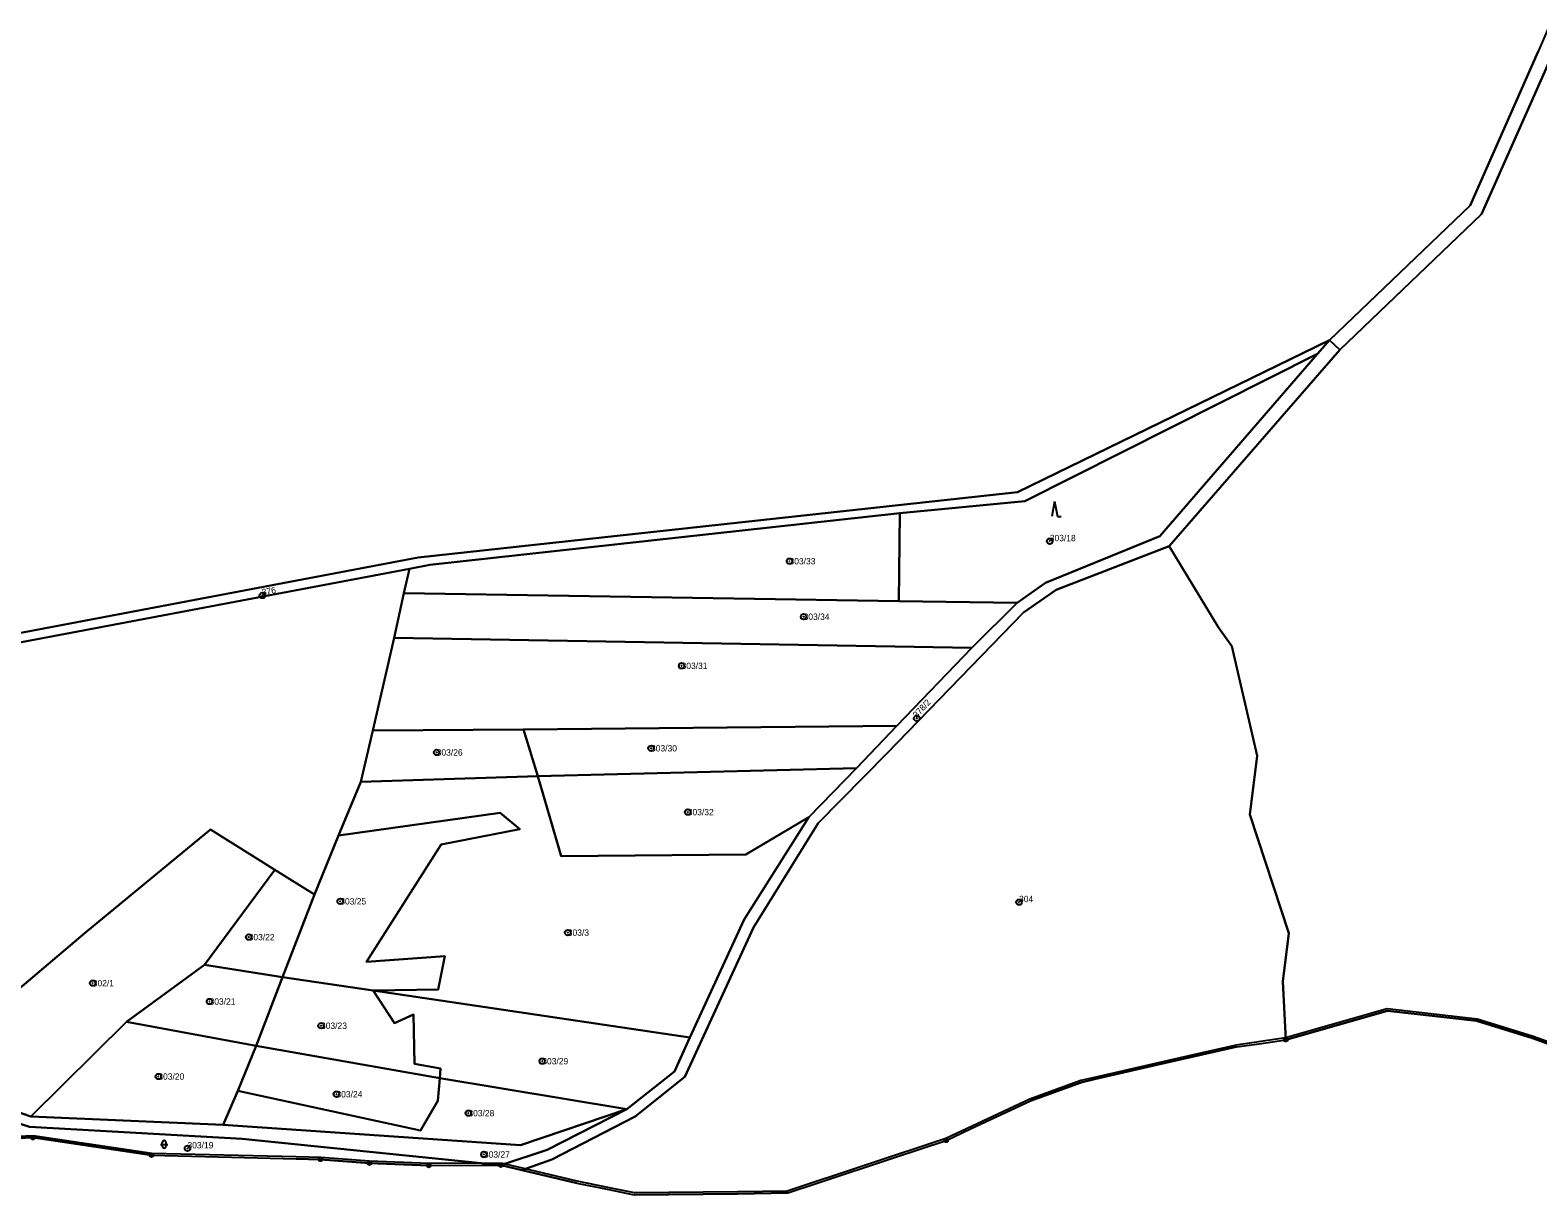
# Model space of a CAD drawing. Extents: x -652854 to -650068, y -1097661 to -1095417.
# Drawn here: x -651701 to -651296.9, y -1097620.5 to -1097308.5 of the extents above; entities that cross this region are included whole.
import ezdxf

# ---------------------------------------------------------------- set-up
doc = ezdxf.new("R2010")
doc.units = 0
for name, color, linetype in [('Definiční body parcel', 7, 'Continuous'), ('Geodetické body', 7, 'Continuous'), ('Hranice obcí', 7, 'Continuous'), ('Hranice parcel', 7, 'Continuous'), ('Obvody jako plochy', 7, 'Continuous'), ('Ostatní hranice', 7, 'Continuous'), ('Parcelní čísla', 7, 'Continuous'), ('Značky kultur', 7, 'Continuous')]:
    doc.layers.add(name, color=color, linetype=linetype)

msp = doc.modelspace()

# ---------------------------------------------------------------- linework, layer by layer
at = {"layer": 'Definiční body parcel'}
for centre, radius in [((-651427.69, -1097445.42), 0.75), ((-651427.69, -1097445.42), 0.0327), ((-651497.45, -1097450.77), 0.75), ((-651497.45, -1097450.77), 0.0327), ((-651638.74, -1097459.95), 0.75), ((-651638.74, -1097459.95), 0.0327), ((-651493.67, -1097465.65), 0.75), ((-651493.67, -1097465.65), 0.0327), ((-651526.38, -1097478.79), 0.75), ((-651526.38, -1097478.79), 0.0327), ((-651463.34, -1097492.88), 0.75), ((-651463.34, -1097492.88), 0.0327), ((-651592.02, -1097502.01), 0.75), ((-651592.02, -1097502.01), 0.0327), ((-651534.57, -1097500.9), 0.75), ((-651534.57, -1097500.9), 0.0327), ((-651524.72, -1097518), 0.75), ((-651524.72, -1097518), 0.0327), ((-651617.87, -1097541.9), 0.75), ((-651617.87, -1097541.9), 0.0327), ((-651435.92, -1097542.13), 0.75), ((-651435.92, -1097542.13), 0.0327), ((-651642.41, -1097551.49), 0.75), ((-651642.41, -1097551.49), 0.0327), ((-651556.88, -1097550.29), 0.75), ((-651556.88, -1097550.29), 0.0327), ((-651684.2, -1097563.83), 0.75), ((-651684.2, -1097563.83), 0.0327), ((-651652.9, -1097568.74), 0.75), ((-651652.9, -1097568.74), 0.0327), ((-651623.02, -1097575.23), 0.75), ((-651623.02, -1097575.23), 0.0327), ((-651563.72, -1097584.73), 0.75), ((-651666.62, -1097588.84), 0.75), ((-651563.72, -1097584.73), 0.0327), ((-651666.62, -1097588.84), 0.0327), ((-651618.89, -1097593.59), 0.75), ((-651618.89, -1097593.59), 0.0327), ((-651583.52, -1097598.66), 0.75), ((-651583.52, -1097598.66), 0.0327), ((-651658.82, -1097608.1), 0.75), ((-651658.82, -1097608.1), 0.0327), ((-651579.35, -1097609.72), 0.75), ((-651579.35, -1097609.72), 0.0327)]:
    msp.add_circle(centre, radius, dxfattribs=at)
at = {"layer": 'Geodetické body'}
for centre, radius in [((-651364.42, -1097579), 0.5), ((-651364.42, -1097579), 0.5), ((-651364.42, -1097579), 0.001), ((-651364.42, -1097579), 0.001), ((-651700.22, -1097605.21), 0.5), ((-651700.22, -1097605.21), 0.001), ((-651455.46, -1097605.96), 0.5), ((-651455.46, -1097605.96), 0.5), ((-651455.46, -1097605.96), 0.001), ((-651455.46, -1097605.96), 0.001), ((-651668.43, -1097609.93), 0.5), ((-651668.43, -1097609.93), 0.001), ((-651623.13, -1097611.06), 0.5), ((-651623.13, -1097611.06), 0.5), ((-651623.13, -1097611.06), 0.001), ((-651623.13, -1097611.06), 0.001), ((-651610.03, -1097612.05), 0.5), ((-651610.03, -1097612.05), 0.5), ((-651610.03, -1097612.05), 0.001), ((-651610.03, -1097612.05), 0.001), ((-651594.11, -1097612.69), 0.5), ((-651594.11, -1097612.69), 0.001), ((-651574.8, -1097612.59), 0.5), ((-651574.8, -1097612.59), 0.5), ((-651574.8, -1097612.59), 0.001), ((-651574.8, -1097612.59), 0.001)]:
    msp.add_circle(centre, radius, dxfattribs=at)
at = {"layer": 'Hranice obcí'}
for p, q in [((-651337.13, -1097571.24), (-651364.42, -1097579)), ((-651313.28, -1097573.95), (-651337.13, -1097571.24)), ((-651298.31, -1097578.57), (-651313.28, -1097573.95)), ((-651377.63, -1097580.93), (-651371.6, -1097580.05)), ((-651371.6, -1097580.05), (-651364.42, -1097579)), ((-651277, -1097586.21), (-651298.31, -1097578.57)), ((-651389.47, -1097583.6), (-651398.89, -1097585.75)), ((-651377.63, -1097580.93), (-651389.47, -1097583.6)), ((-651398.89, -1097585.75), (-651415.59, -1097589.57)), ((-651419.25, -1097590.4), (-651432.82, -1097595.37)), ((-651415.59, -1097589.57), (-651419.25, -1097590.4)), ((-651448.91, -1097602.9), (-651432.82, -1097595.37)), ((-651455.46, -1097605.96), (-651448.91, -1097602.9)), ((-651700.22, -1097605.21), (-651729.58, -1097606.47)), ((-651668.43, -1097609.93), (-651700.22, -1097605.21)), ((-651469.31, -1097610.54), (-651455.46, -1097605.96)), ((-651668.43, -1097609.93), (-651647.03, -1097610.47)), ((-651647.03, -1097610.47), (-651629.7, -1097610.9)), ((-651623.13, -1097611.06), (-651629.7, -1097610.9)), ((-651610.03, -1097612.05), (-651623.13, -1097611.06)), ((-651594.11, -1097612.69), (-651610.03, -1097612.05)), ((-651594.11, -1097612.69), (-651579.78, -1097612.61)), ((-651579.78, -1097612.61), (-651574.8, -1097612.59)), ((-651569.22, -1097613.9), (-651574.8, -1097612.59)), ((-651490.01, -1097617.39), (-651469.31, -1097610.54)), ((-651554.46, -1097617.39), (-651569.22, -1097613.9)), ((-651554.46, -1097617.39), (-651546.31, -1097619.06)), ((-651546.31, -1097619.06), (-651539.06, -1097620.54)), ((-651511.38, -1097620.25), (-651539.06, -1097620.54)), ((-651497.93, -1097620.01), (-651511.38, -1097620.25)), ((-651497.93, -1097620.01), (-651490.01, -1097617.39))]:
    msp.add_line(p, q, dxfattribs=at)
at = {"layer": 'Hranice parcel'}
for p, q in [((-651296.82, -1097314.26), (-651315.05, -1097355.46)), ((-651292.83, -1097314.79), (-651311.99, -1097357.78)), ((-651315.05, -1097355.46), (-651352.74, -1097391.59)), ((-651311.99, -1097357.78), (-651349.9, -1097394.12)), ((-651352.74, -1097391.59), (-651436.3, -1097432.32)), ((-651349.9, -1097394.12), (-651395.72, -1097446.74)), ((-651352.74, -1097391.59), (-651355.9, -1097395.18)), ((-651352.74, -1097391.59), (-651349.9, -1097394.12)), ((-651355.9, -1097395.18), (-651434.39, -1097434.71)), ((-651398.15, -1097444.11), (-651355.9, -1097395.18)), ((-651436.3, -1097432.32), (-651530.5, -1097442.54)), ((-651434.39, -1097434.71), (-651467.92, -1097437.92)), ((-651467.92, -1097437.92), (-651593.84, -1097451.76)), ((-651468.15, -1097461.46), (-651467.92, -1097437.92)), ((-651530.5, -1097442.54), (-651596.98, -1097449.79)), ((-651428.8, -1097456.57), (-651398.15, -1097444.11)), ((-651395.72, -1097446.74), (-651426.01, -1097458.44)), ((-651395.72, -1097446.74), (-651382.47, -1097468.55)), ((-651596.98, -1097449.79), (-651728.02, -1097474.61)), ((-651727.11, -1097476.95), (-651599.33, -1097452.83)), ((-651599.33, -1097452.83), (-651600.83, -1097459.37)), ((-651593.84, -1097451.76), (-651599.33, -1097452.83)), ((-651436.45, -1097461.97), (-651428.8, -1097456.57)), ((-651426.01, -1097458.44), (-651434.69, -1097464.56)), ((-651600.83, -1097459.37), (-651603.38, -1097471.34)), ((-651468.15, -1097461.46), (-651600.83, -1097459.37)), ((-651436.45, -1097461.97), (-651468.15, -1097461.46)), ((-651448.61, -1097473.99), (-651436.45, -1097461.97)), ((-651434.69, -1097464.56), (-651471.39, -1097502.28)), ((-651382.47, -1097468.55), (-651378.9, -1097473.52)), ((-651603.38, -1097471.34), (-651609.14, -1097496.17)), ((-651603.38, -1097471.34), (-651448.61, -1097473.99)), ((-651468.7, -1097494.92), (-651448.61, -1097473.99)), ((-651378.9, -1097473.52), (-651372.12, -1097502.94)), ((-651568.76, -1097495.83), (-651468.7, -1097494.92)), ((-651479.48, -1097506.25), (-651468.7, -1097494.92)), ((-651609.14, -1097496.17), (-651612.36, -1097509.88)), ((-651609.14, -1097496.17), (-651568.76, -1097495.83)), ((-651568.76, -1097495.83), (-651564.92, -1097508.39)), ((-651471.39, -1097502.28), (-651489.8, -1097520.96)), ((-651372.12, -1097502.94), (-651374.05, -1097518.63)), ((-651564.92, -1097508.39), (-651479.48, -1097506.25)), ((-651492.25, -1097519.39), (-651479.48, -1097506.25)), ((-651612.36, -1097509.88), (-651618.36, -1097524.24)), ((-651612.36, -1097509.88), (-651564.92, -1097508.39)), ((-651564.92, -1097508.39), (-651558.68, -1097529.83)), ((-651618.36, -1097524.24), (-651575.04, -1097518.22)), ((-651575.04, -1097518.22), (-651569.77, -1097522.59)), ((-651509.62, -1097546.74), (-651492.25, -1097519.39)), ((-651509.13, -1097529.39), (-651492.25, -1097519.39)), ((-651374.05, -1097518.63), (-651363.62, -1097550.42)), ((-651652.64, -1097522.63), (-651686.19, -1097550.23)), ((-651635.4, -1097533.46), (-651652.64, -1097522.63)), ((-651569.77, -1097522.59), (-651590.8, -1097526.64)), ((-651489.8, -1097520.96), (-651507.07, -1097548.89)), ((-651618.36, -1097524.24), (-651624.76, -1097540.1)), ((-651590.8, -1097526.64), (-651610.85, -1097558.14)), ((-651558.68, -1097529.83), (-651509.13, -1097529.39)), ((-651654.22, -1097558.94), (-651635.4, -1097533.46)), ((-651624.76, -1097540.1), (-651635.4, -1097533.46)), ((-651633.37, -1097562.19), (-651624.76, -1097540.1)), ((-651524.13, -1097578.41), (-651509.62, -1097546.74)), ((-651686.19, -1097550.23), (-651716.83, -1097576.15)), ((-651507.07, -1097548.89), (-651525.51, -1097588.9)), ((-651363.62, -1097550.42), (-651365.24, -1097563.35)), ((-651675.12, -1097574.18), (-651654.22, -1097558.94)), ((-651654.22, -1097558.94), (-651633.37, -1097562.19)), ((-651610.85, -1097558.14), (-651589.85, -1097556.59)), ((-651589.85, -1097556.59), (-651591.64, -1097565.54)), ((-651633.37, -1097562.19), (-651640.4, -1097580.6)), ((-651609.08, -1097565.78), (-651633.37, -1097562.19)), ((-651365.24, -1097563.35), (-651364.42, -1097579)), ((-651591.64, -1097565.54), (-651609.08, -1097565.78)), ((-651603.29, -1097574.58), (-651609.08, -1097565.78)), ((-651609.08, -1097565.78), (-651524.13, -1097578.41)), ((-651598.19, -1097572.26), (-651603.29, -1097574.58)), ((-651597.93, -1097585.41), (-651598.19, -1097572.26)), ((-651675.12, -1097574.18), (-651700.83, -1097599.54)), ((-651640.4, -1097580.6), (-651675.12, -1097574.18)), ((-651528.3, -1097587.52), (-651524.13, -1097578.41)), ((-651645.36, -1097592.65), (-651640.4, -1097580.6)), ((-651640.4, -1097580.6), (-651591.15, -1097589.24)), ((-651590.96, -1097586.72), (-651597.93, -1097585.41)), ((-651591.15, -1097589.24), (-651590.96, -1097586.72)), ((-651541.07, -1097597.57), (-651528.3, -1097587.52)), ((-651591.15, -1097589.24), (-651591.72, -1097595.34)), ((-651541.07, -1097597.57), (-651591.15, -1097589.24)), ((-651525.51, -1097588.9), (-651538.78, -1097599.58)), ((-651715.83, -1097594.35), (-651700.83, -1097599.54)), ((-651649.26, -1097601.77), (-651645.36, -1097592.65)), ((-651596.36, -1097603.33), (-651645.36, -1097592.65)), ((-651591.72, -1097595.34), (-651596.36, -1097603.33)), ((-651700.83, -1097599.54), (-651649.26, -1097601.77)), ((-651569.57, -1097607.22), (-651541.07, -1097597.57)), ((-651562.37, -1097608.51), (-651541.07, -1097597.57)), ((-651538.78, -1097599.58), (-651561.16, -1097611.04)), ((-651701.14, -1097602.34), (-651644.13, -1097605.5)), ((-651649.26, -1097601.77), (-651569.57, -1097607.22)), ((-651644.13, -1097605.5), (-651574.8, -1097612.59)), ((-651574.8, -1097612.59), (-651562.37, -1097608.51)), ((-651561.16, -1097611.04), (-651569.22, -1097613.9))]:
    msp.add_line(p, q, dxfattribs=at)
at = {"layer": 'Obvody jako plochy'}
for points in [[(-651262.01, -1097240.19), (-651277.09, -1097269.24), (-651280.03, -1097275.19), (-651296.82, -1097314.26), (-651315.05, -1097355.46), (-651352.74, -1097391.59), (-651349.9, -1097394.12), (-651311.99, -1097357.78), (-651292.83, -1097314.79), (-651276.57, -1097276.23), (-651259.51, -1097243.85), (-651255.47, -1097239.3), (-651252.1, -1097236.08), (-651239.51, -1097222.83), (-651229.64, -1097212.45), (-651222.78, -1097208.09), (-651205.8, -1097197.3), (-651173.63, -1097177.36), (-651176.11, -1097174.26), (-651231.07, -1097209.73)], [(-651355.9, -1097395.18), (-651352.74, -1097391.59), (-651436.3, -1097432.32), (-651530.5, -1097442.54), (-651596.98, -1097449.79), (-651728.02, -1097474.61), (-651825.38, -1097476.82), (-651825.44, -1097478.37), (-651825.47, -1097479.81), (-651798.82, -1097479.19), (-651727.11, -1097476.95), (-651599.33, -1097452.83), (-651593.84, -1097451.76), (-651467.92, -1097437.92), (-651434.39, -1097434.71)], [(-651541.07, -1097597.57), (-651562.37, -1097608.51), (-651574.8, -1097612.59), (-651569.22, -1097613.9), (-651561.16, -1097611.04), (-651538.78, -1097599.58), (-651525.51, -1097588.9), (-651507.07, -1097548.89), (-651489.8, -1097520.96), (-651471.39, -1097502.28), (-651434.69, -1097464.56), (-651426.01, -1097458.44), (-651395.72, -1097446.74), (-651349.9, -1097394.12), (-651352.74, -1097391.59), (-651355.9, -1097395.18), (-651398.15, -1097444.11), (-651428.8, -1097456.57), (-651436.45, -1097461.97), (-651448.61, -1097473.99), (-651468.7, -1097494.92), (-651479.48, -1097506.25), (-651492.25, -1097519.39), (-651509.62, -1097546.74), (-651524.13, -1097578.41), (-651528.3, -1097587.52)], [(-651428.8, -1097456.57), (-651398.15, -1097444.11), (-651355.9, -1097395.18), (-651434.39, -1097434.71), (-651467.92, -1097437.92), (-651468.15, -1097461.46), (-651436.45, -1097461.97)], [(-651593.84, -1097451.76), (-651599.33, -1097452.83), (-651600.83, -1097459.37), (-651468.15, -1097461.46), (-651467.92, -1097437.92)], [(-651561.16, -1097611.04), (-651569.22, -1097613.9), (-651554.46, -1097617.39), (-651546.31, -1097619.06), (-651539.06, -1097620.54), (-651511.38, -1097620.25), (-651497.93, -1097620.01), (-651490.01, -1097617.39), (-651469.31, -1097610.54), (-651455.46, -1097605.96), (-651448.91, -1097602.9), (-651432.82, -1097595.37), (-651419.25, -1097590.4), (-651415.59, -1097589.57), (-651398.89, -1097585.75), (-651389.47, -1097583.6), (-651377.63, -1097580.93), (-651371.6, -1097580.05), (-651364.42, -1097579), (-651365.24, -1097563.35), (-651363.62, -1097550.42), (-651374.05, -1097518.63), (-651372.12, -1097502.94), (-651378.9, -1097473.52), (-651382.47, -1097468.55), (-651395.72, -1097446.74), (-651426.01, -1097458.44), (-651434.69, -1097464.56), (-651471.39, -1097502.28), (-651489.8, -1097520.96), (-651507.07, -1097548.89), (-651525.51, -1097588.9), (-651538.78, -1097599.58)], [(-651600.83, -1097459.37), (-651603.38, -1097471.34), (-651448.61, -1097473.99), (-651436.45, -1097461.97), (-651468.15, -1097461.46)], [(-651603.38, -1097471.34), (-651609.14, -1097496.17), (-651568.76, -1097495.83), (-651468.7, -1097494.92), (-651448.61, -1097473.99)], [(-651479.48, -1097506.25), (-651468.7, -1097494.92), (-651568.76, -1097495.83), (-651564.92, -1097508.39)], [(-651609.14, -1097496.17), (-651612.36, -1097509.88), (-651564.92, -1097508.39), (-651568.76, -1097495.83)], [(-651492.25, -1097519.39), (-651479.48, -1097506.25), (-651564.92, -1097508.39), (-651558.68, -1097529.83), (-651509.13, -1097529.39)], [(-651524.13, -1097578.41), (-651509.62, -1097546.74), (-651492.25, -1097519.39), (-651509.13, -1097529.39), (-651558.68, -1097529.83), (-651564.92, -1097508.39), (-651612.36, -1097509.88), (-651618.36, -1097524.24), (-651575.04, -1097518.22), (-651569.77, -1097522.59), (-651590.8, -1097526.64), (-651610.85, -1097558.14), (-651589.85, -1097556.59), (-651591.64, -1097565.54), (-651609.08, -1097565.78)], [(-651618.36, -1097524.24), (-651624.76, -1097540.1), (-651633.37, -1097562.19), (-651609.08, -1097565.78), (-651591.64, -1097565.54), (-651589.85, -1097556.59), (-651610.85, -1097558.14), (-651590.8, -1097526.64), (-651569.77, -1097522.59), (-651575.04, -1097518.22)], [(-651716.83, -1097576.15), (-651723.58, -1097590.51), (-651715.83, -1097594.35), (-651700.83, -1097599.54), (-651675.12, -1097574.18), (-651654.22, -1097558.94), (-651635.4, -1097533.46), (-651652.64, -1097522.63), (-651686.19, -1097550.23)], [(-651624.76, -1097540.1), (-651635.4, -1097533.46), (-651654.22, -1097558.94), (-651633.37, -1097562.19)], [(-651633.37, -1097562.19), (-651654.22, -1097558.94), (-651675.12, -1097574.18), (-651640.4, -1097580.6)], [(-651633.37, -1097562.19), (-651640.4, -1097580.6), (-651591.15, -1097589.24), (-651590.96, -1097586.72), (-651597.93, -1097585.41), (-651598.19, -1097572.26), (-651603.29, -1097574.58), (-651609.08, -1097565.78)], [(-651541.07, -1097597.57), (-651528.3, -1097587.52), (-651524.13, -1097578.41), (-651609.08, -1097565.78), (-651603.29, -1097574.58), (-651598.19, -1097572.26), (-651597.93, -1097585.41), (-651590.96, -1097586.72), (-651591.15, -1097589.24)], [(-651700.83, -1097599.54), (-651649.26, -1097601.77), (-651645.36, -1097592.65), (-651640.4, -1097580.6), (-651675.12, -1097574.18)], [(-651645.36, -1097592.65), (-651596.36, -1097603.33), (-651591.72, -1097595.34), (-651591.15, -1097589.24), (-651640.4, -1097580.6)], [(-651725.08, -1097593.81), (-651716.15, -1097597.61), (-651701.14, -1097602.34), (-651644.13, -1097605.5), (-651574.8, -1097612.59), (-651562.37, -1097608.51), (-651541.07, -1097597.57), (-651569.57, -1097607.22), (-651649.26, -1097601.77), (-651700.83, -1097599.54), (-651715.83, -1097594.35), (-651723.58, -1097590.51)], [(-651649.26, -1097601.77), (-651569.57, -1097607.22), (-651541.07, -1097597.57), (-651591.15, -1097589.24), (-651591.72, -1097595.34), (-651596.36, -1097603.33), (-651645.36, -1097592.65)], [(-651725.08, -1097593.81), (-651729.58, -1097606.47), (-651700.22, -1097605.21), (-651668.43, -1097609.93), (-651647.03, -1097610.47), (-651629.7, -1097610.9), (-651623.13, -1097611.06), (-651610.03, -1097612.05), (-651594.11, -1097612.69), (-651579.78, -1097612.61), (-651574.8, -1097612.59), (-651644.13, -1097605.5), (-651701.14, -1097602.34), (-651716.15, -1097597.61)]]:
    msp.add_lwpolyline(points, close=True, dxfattribs=at)
for points in [[(-651728.02, -1097474.61), (-651596.98, -1097449.79), (-651530.5, -1097442.54), (-651436.3, -1097432.32), (-651352.74, -1097391.59), (-651315.05, -1097355.46), (-651296.82, -1097314.26)], [(-651292.83, -1097314.79), (-651311.99, -1097357.78), (-651349.9, -1097394.12), (-651395.72, -1097446.74), (-651382.47, -1097468.55), (-651378.9, -1097473.52), (-651372.12, -1097502.94), (-651374.05, -1097518.63), (-651363.62, -1097550.42), (-651365.24, -1097563.35), (-651364.42, -1097579), (-651337.13, -1097571.24), (-651313.28, -1097573.95), (-651298.31, -1097578.57), (-651277, -1097586.21)], [(-651716.83, -1097576.15), (-651686.19, -1097550.23), (-651652.64, -1097522.63), (-651635.4, -1097533.46), (-651624.76, -1097540.1), (-651618.36, -1097524.24), (-651612.36, -1097509.88), (-651609.14, -1097496.17), (-651603.38, -1097471.34), (-651600.83, -1097459.37), (-651599.33, -1097452.83), (-651727.11, -1097476.95)]]:
    msp.add_lwpolyline(points, dxfattribs=at)
at = {"layer": 'Ostatní hranice'}
for p, q in [((-651337.22, -1097570.74), (-651364.51, -1097578.5)), ((-651313.17, -1097573.45), (-651337.22, -1097570.74)), ((-651298.12, -1097578.1), (-651313.17, -1097573.45)), ((-651364.51, -1097578.5), (-651377.73, -1097580.43)), ((-651276.79, -1097585.75), (-651298.12, -1097578.1)), ((-651389.6, -1097583.11), (-651398.99, -1097585.25)), ((-651377.73, -1097580.43), (-651389.6, -1097583.11)), ((-651398.99, -1097585.25), (-651415.7, -1097589.07)), ((-651419.41, -1097589.92), (-651433, -1097594.9)), ((-651415.7, -1097589.07), (-651419.41, -1097589.92)), ((-651433, -1097594.9), (-651455.59, -1097605.47)), ((-651700.16, -1097604.7), (-651729.41, -1097605.99)), ((-651668.35, -1097609.43), (-651700.16, -1097604.7)), ((-651455.59, -1097605.47), (-651498.05, -1097619.52)), ((-651629.69, -1097610.39), (-651668.35, -1097609.43)), ((-651623.11, -1097610.55), (-651629.69, -1097610.39)), ((-651610, -1097611.54), (-651623.11, -1097610.55)), ((-651594.1, -1097612.18), (-651610, -1097611.54)), ((-651574.72, -1097612.09), (-651594.1, -1097612.18)), ((-651569.06, -1097613.41), (-651574.72, -1097612.09)), ((-651554.34, -1097616.9), (-651569.06, -1097613.41)), ((-651546.18, -1097618.57), (-651554.34, -1097616.9)), ((-651538.96, -1097620.04), (-651546.18, -1097618.57)), ((-651511.37, -1097619.74), (-651538.96, -1097620.04)), ((-651498.05, -1097619.52), (-651511.37, -1097619.74))]:
    msp.add_line(p, q, dxfattribs=at)
at = {"layer": 'Značky kultur'}
for p, q in [((-651426.382, -1097434.759), (-651427.115, -1097438.759)), ((-651426.382, -1097434.759), (-651425.649, -1097438.759)), ((-651425.649, -1097438.759), (-651424.649, -1097438.759)), ((-651666.07, -1097607.02), (-651664.07, -1097607.02)), ((-651665.57, -1097607.52), (-651665.57, -1097606.52)), ((-651664.57, -1097607.52), (-651664.57, -1097606.52))]:
    msp.add_line(p, q, dxfattribs=at)
for centre, start, end in [((-651665.07, -1097606.52), 0, 180), ((-651665.07, -1097607.52), 180, 0)]:
    msp.add_arc(centre, 0.5, start, end, dxfattribs=at)

# ---------------------------------------------------------------- texts
at = {"layer": 'Parcelní čísla'}
for s, p in [('303/18', (-651427.69, -1097445.42)), ('303/33', (-651497.45, -1097451.62)), ('303/34', (-651493.67, -1097466.5)), ('303/31', (-651526.38, -1097479.64)), ('303/26', (-651592.02, -1097502.86)), ('303/30', (-651534.57, -1097501.75)), ('303/32', (-651524.72, -1097518.85)), ('303/25', (-651617.87, -1097542.75)), ('304', (-651435.92, -1097542.13)), ('303/22', (-651642.41, -1097552.34)), ('303/3', (-651556.88, -1097551.14)), ('302/1', (-651684.2, -1097564.68)), ('303/21', (-651652.9, -1097569.59)), ('303/23', (-651623.02, -1097576.08)), ('303/29', (-651563.72, -1097585.58)), ('303/20', (-651666.62, -1097589.69)), ('303/24', (-651618.89, -1097594.44)), ('303/28', (-651583.52, -1097599.51)), ('303/19', (-651658.82, -1097608.1)), ('303/27', (-651579.35, -1097610.57))]:
    msp.add_text(s, height=1.7, dxfattribs=at).set_placement(p)
for s, rotation, p in [('376', 10.008, (-651638.74, -1097459.95)), ('378/2', 46.773, (-651463.34, -1097492.88))]:
    msp.add_text(s, height=1.7, rotation=rotation, dxfattribs=at).set_placement(p)

doc.saveas('drawing.dxf')
